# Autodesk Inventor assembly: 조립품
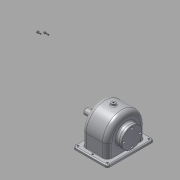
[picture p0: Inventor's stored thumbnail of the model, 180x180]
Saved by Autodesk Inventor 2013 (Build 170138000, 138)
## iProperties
Created: 2015-09
Part Number: 조립품
Document SubType Name: Assembly
Designer: user-11
Author: user-11
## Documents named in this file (14)
- C:\Users\user-11\Desktop\450907V1003\조립품.iam
- C:\Users\user-11\Desktop\450907V1003\본체.ipt
- C:\Users\user-11\Desktop\450907V1003\V-벨트풀리.ipt
- C:\Users\user-11\Desktop\450907V1003\뒤커버.ipt
- C:\Users\user-11\Desktop\450907V1003\멈춤나사 - M4x10.ipt
- C:\Users\user-11\Desktop\450907V1003\베어링 6203.ipt
- C:\Users\user-11\Desktop\450907V1003\볼트 M3 x 8.ipt
- C:\Users\user-11\Desktop\450907V1003\볼트 M3 x 10.ipt
- C:\Users\user-11\Desktop\450907V1003\스퍼기어.ipt
- C:\Users\user-11\Desktop\450907V1003\앞커버.ipt
- C:\Users\user-11\Desktop\450907V1003\오일 실 17 32 8.ipt
- C:\Users\user-11\Desktop\450907V1003\축.ipt
- C:\Users\user-11\Desktop\450907V1003\키 - 5 x 5 x 18.ipt
- C:\Users\user-11\Desktop\450907V1003\키 - 6 x 6 x 22.ipt
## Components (3 placed, 3 different names)
1. V-벨트풀리:1
2. ISO 4762 M3 x 8:1
3. ISO 4762 M3 x 10:1
